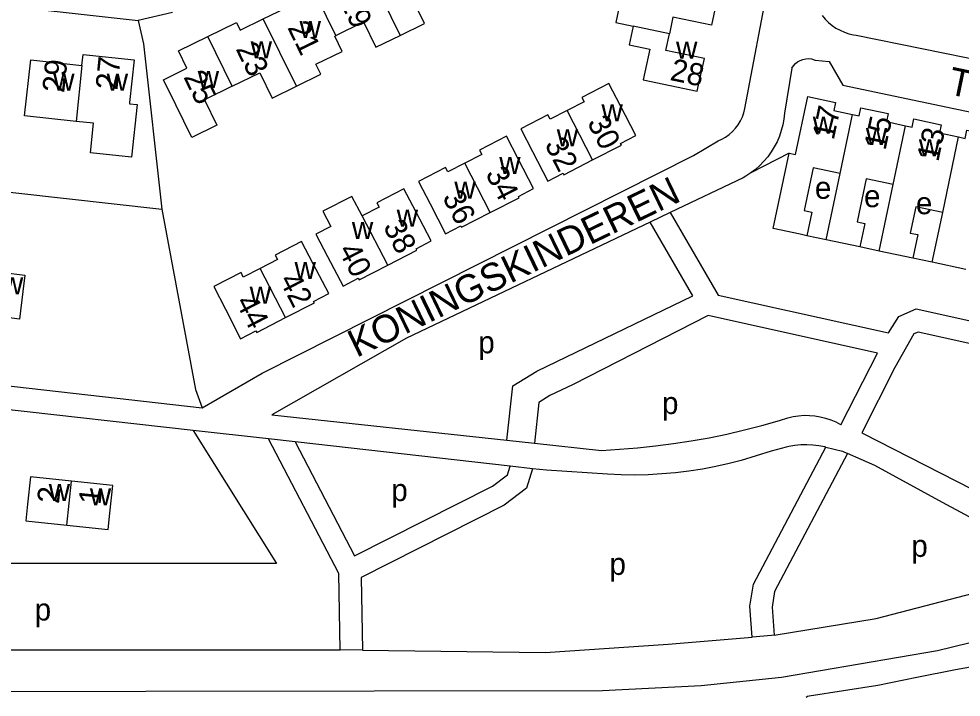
# Model space of a CAD drawing. Extents: x 159441 to 162086, y 388175 to 389787.
# Drawn here: x 161523.9 to 161694.2, y 388347.3 to 388469.9 of the extents above; entities that cross this region are included whole.
import ezdxf

# ---------------------------------------------------------------- set-up
doc = ezdxf.new("R2010")
doc.units = 0
for name, color, linetype in [('BLT_Basislijn', 7, 'Continuous'), ('BLT_Bebouwing', 7, 'Continuous'), ('BLT_Centroide', 7, 'Continuous'), ('BLT_Huisnummer', 7, 'Continuous'), ('BLT_Huisnummer_ tussenligend', 7, 'Continuous'), ('BLT_Onderverdeling_panden', 7, 'Continuous'), ('BLT_Straatnaam', 7, 'Continuous')]:
    doc.layers.add(name, color=color, linetype=linetype)

msp = doc.modelspace()

# ---------------------------------------------------------------- linework, layer by layer
at = {"layer": 'BLT_Basislijn'}
for p, q in [((161663.59, 388460.99), (161662.25, 388452.85)), ((161641.62, 388434.91), (161638, 388433.18)), ((161555.41, 388395.51), (161495.67, 388402.23)), ((161573.83, 388393.44), (161569.03, 388393.98)), ((161612.09, 388393.76), (161617.07, 388393.23)), ((161616.74, 388388.61), (161612.7, 388389.07)), ((161585.99, 388355.8), (161581.99, 388355.85))]:
    msp.add_line(p, q, dxfattribs=at)
for points in [[(161557.01, 388399.62), (161567.87, 388405.86), (161645.85, 388445.21), (161650.29, 388447.83), (161650.94, 388448.13), (161651.64, 388448.53), (161652.29, 388449), (161652.89, 388449.54), (161653.43, 388450.12), (161653.91, 388450.77), (161654.33, 388451.45), (161654.68, 388452.18), (161654.95, 388452.93), (161655.14, 388453.71), (161663.91, 388500)], [(161328.88, 388459.92), (161332.73, 388492.8), (161435.01, 388481.49), (161524.85, 388471.88), (161545.47, 388469.62)], [(161551.69, 388471.03), (161545.47, 388469.62)], [(161545.47, 388469.62), (161546.41, 388465.4), (161549.75, 388435.53)], [(161669.1, 388470.52), (161669.64, 388469.86), (161670.23, 388469.26), (161670.88, 388468.71), (161671.58, 388468.23), (161672.33, 388467.82), (161673.1, 388467.47), (161673.91, 388467.21), (161674.74, 388467.02), (161675.22, 388466.94), (161698.95, 388462.12)], [(161663.59, 388460.99), (161663.89, 388461.43), (161664.24, 388461.81), (161664.65, 388462.13), (161665.11, 388462.38), (161665.6, 388462.56), (161666.11, 388462.67), (161666.63, 388462.7), (161667.15, 388462.64), (161667.65, 388462.51), (161667.8, 388462.45)], [(161667.8, 388462.45), (161670.33, 388462.2), (161672.85, 388457.91), (161744.15, 388442.93)], [(161328.88, 388459.92), (161341.81, 388458.77), (161549.75, 388435.53)], [(161662.25, 388452.85), (161662.14, 388451.79), (161661.95, 388450.74), (161661.69, 388449.7), (161661.35, 388448.69), (161660.93, 388447.7), (161660.44, 388446.75), (161659.88, 388445.84), (161659.26, 388444.97), (161658.57, 388444.15), (161657.82, 388443.39), (161657.02, 388442.68), (161656.17, 388442.04)], [(161663.12, 388445.64), (161656.17, 388442.04)], [(161641.62, 388434.91), (161650.27, 388419.97), (161681.07, 388413.13), (161682.92, 388416.13), (161686.07, 388417.48), (161748.77, 388403.58), (161749.41, 388403.67), (161750.3, 388405.26), (161762.33, 388432.28), (161760.67, 388433.58), (161755.49, 388443.93)], [(161656.17, 388442.04), (161655.27, 388441.46), (161654.78, 388441.18), (161641.62, 388434.91)], [(161549.75, 388435.53), (161555.81, 388402.9), (161557.01, 388399.62)], [(161638, 388433.18), (161593.99, 388412.2), (161569.65, 388398.33), (161612.09, 388393.76)], [(161612.09, 388393.76), (161613.18, 388403.56), (161617.5, 388406.22), (161645.73, 388419.84), (161638, 388433.18)], [(161669.81, 388429.96), (161666.29, 388430.71)], [(161679.39, 388427.93), (161675.87, 388428.68)], [(161688.96, 388425.9), (161685.45, 388426.65)], [(161325.51, 388426.05), (161325.92, 388425.85), (161557.01, 388399.62)], [(161617.07, 388393.23), (161629.18, 388391.92), (161632.45, 388392.11), (161635.71, 388392.37), (161638.96, 388392.71), (161642.2, 388393.13), (161645.43, 388393.63), (161648.65, 388394.21), (161651.86, 388394.87), (161655.05, 388395.61), (161658.21, 388396.42), (161661.36, 388397.31), (161662.9, 388397.78), (161663.86, 388398.01), (161664.83, 388398.17), (161665.81, 388398.25), (161666.79, 388398.24), (161667.77, 388398.16), (161668.74, 388398), (161669.7, 388397.76), (161670.63, 388397.45), (161671.53, 388397.05), (161672.4, 388396.59), (161672.49, 388396.54), (161679.08, 388409.47), (161648.47, 388416.28), (161624.07, 388403.85), (161619.89, 388401.82), (161617.88, 388400.59), (161617.07, 388393.23)], [(161748.62, 388399.51), (161686.46, 388413.3), (161685.66, 388412.95), (161682.25, 388406.88), (161676.24, 388395.08), (161704.72, 388380.56)], [(161825.3, 388398.51), (161820.15, 388396.26), (161815.22, 388394.54), (161712.84, 388361.31), (161689.93, 388355.71), (161661.73, 388350.85), (161647.19, 388349.34), (161629.36, 388348.46), (161381.74, 388348.09), (161372.15, 388347.92), (161363.21, 388348.43), (161354.77, 388349.2), (161344.3, 388349.46), (161332.03, 388349.71), (161319.76, 388350.22), (161309.54, 388350.22), (161304.37, 388350.34)], [(161555.41, 388395.51), (161570.48, 388371.48), (161500.96, 388371.48), (161494.67, 388371.46)], [(161569.03, 388393.98), (161555.41, 388395.51)], [(161581.99, 388355.85), (161581.74, 388369.68), (161569.03, 388393.98)], [(161612.7, 388389.07), (161573.83, 388393.44)], [(161573.83, 388393.44), (161584.59, 388372.86), (161609.5, 388385.45), (161612.23, 388387.5), (161612.7, 388389.07)], [(161669.72, 388392.49), (161669.54, 388392.54), (161668.46, 388392.75), (161667.38, 388392.87), (161666.29, 388392.92), (161665.21, 388392.89), (161664.12, 388392.78), (161663.05, 388392.59), (161662.6, 388392.48), (161659.86, 388391.75), (161657.14, 388390.95), (161654.45, 388390.07), (161652.26, 388389.52), (161649.85, 388388.99), (161647.44, 388388.53), (161645.01, 388388.16), (161642.56, 388387.86), (161640.12, 388387.65), (161637.66, 388387.52), (161635.2, 388387.46), (161632.74, 388387.49), (161630.29, 388387.59), (161619.28, 388388.33), (161616.74, 388388.61)], [(161656.41, 388358.15), (161656.01, 388363.79), (161656.66, 388367.73), (161669.72, 388392.49)], [(161673.65, 388391.36), (161660.5, 388366.43), (161660.03, 388363.6), (161660.39, 388358.51)], [(161660.39, 388358.51), (161678.84, 388361.51), (161702.48, 388367.68), (161705.14, 388368.97), (161705.58, 388369.16), (161705.98, 388369.43), (161706.33, 388369.76), (161706.62, 388370.15), (161706.84, 388370.57), (161706.99, 388371.03), (161707.06, 388371.51), (161707.05, 388371.99), (161706.97, 388372.46), (161706.8, 388372.91), (161706.57, 388373.33), (161706.26, 388373.71), (161705.9, 388374.03), (161705.64, 388374.2), (161700.61, 388377.23), (161690.86, 388382.48), (161678.59, 388389.18), (161673.65, 388391.36)], [(161669.72, 388392.49), (161672.77, 388391.76), (161673.65, 388391.36)], [(161666.18, 388347.32), (161666.21, 388347.35), (161666.45, 388347.5), (161666.73, 388347.57), (161679.17, 388349.49), (161686.18, 388350.96), (161693.19, 388352.32), (161696.56, 388352.91), (161721.71, 388357.07), (161772.64, 388373.89), (161801.25, 388383.37), (161821.16, 388389.95)], [(161616.74, 388388.61), (161615.68, 388385.09), (161611.62, 388382.04), (161585.75, 388368.97), (161585.99, 388355.8)], [(161660.39, 388358.51), (161659.93, 388358.44), (161656.41, 388358.15)], [(161585.99, 388355.8), (161619.04, 388355.37), (161641.27, 388356.9), (161656.41, 388358.15)], [(161364.69, 388356.62), (161369.6, 388356.36), (161383.15, 388356.1), (161390.81, 388356.36), (161502.75, 388355.88), (161579.94, 388355.88), (161581.99, 388355.85)]]:
    msp.add_lwpolyline(points, dxfattribs=at)
at = {"layer": 'BLT_Bebouwing'}
for p, q in [((161526.04, 388462.49), (161535.29, 388461.49)), ((161669.81, 388429.96), (161672.33, 388441.97)), ((161679.39, 388427.93), (161681.92, 388439.95)), ((161688.96, 388425.9), (161690.87, 388434.93))]:
    msp.add_line(p, q, dxfattribs=at)
for points in [[(161592.79, 388466.9), (161597.23, 388469.07), (161594.99, 388473.64), (161599.98, 388476.08)], [(161636.78, 388477.35), (161635.64, 388471.99), (161632.53, 388472.65), (161631.8, 388469.22), (161634.91, 388468.56)], [(161568.05, 388469.87), (161572.19, 388471.9), (161571.52, 388473.28), (161576.81, 388475.88)], [(161650.3, 388474.49), (161649.08, 388468.75), (161642.12, 388470.22), (161641.48, 388467.2)], [(161558.05, 388466.69), (161563.24, 388469.23), (161563.91, 388467.85), (161568.05, 388469.87)], [(161581.21, 388466.9), (161586.2, 388469.34), (161588.44, 388464.76), (161592.79, 388466.9)], [(161634.91, 388468.56), (161634.2, 388465.2), (161637.93, 388464.42), (161636.76, 388458.86), (161641.62, 388457.84), (161646.52, 388456.81), (161647.81, 388462.71), (161640.84, 388464.18), (161641.48, 388467.2)], [(161562.44, 388457.71), (161557.45, 388455.27), (161559.7, 388450.69), (161555.16, 388448.47), (161552.25, 388454.37), (161550.04, 388458.86), (161554.29, 388460.96), (161552.74, 388464.09), (161558.05, 388466.69)], [(161574.07, 388457.73), (161578.47, 388459.88), (161577.58, 388461.7), (161582.36, 388464), (161580.99, 388466.79), (161581.21, 388466.9)], [(161534.27, 388451.37), (161524.94, 388452.38), (161526.04, 388462.49)], [(161535.29, 388461.49), (161535.51, 388463.48), (161544.75, 388462.48), (161543.92, 388454.8), (161543.89, 388454.54), (161545.3, 388454.39), (161544.27, 388444.89), (161536.85, 388445.69), (161537.42, 388451.03), (161534.27, 388451.37)], [(161562.44, 388457.71), (161567.43, 388460.15), (161569.67, 388455.57), (161574.07, 388457.73)], [(161627.6, 388444.39), (161632.81, 388447.07), (161632.65, 388447.39), (161635.4, 388448.8), (161632.64, 388454.17), (161630.55, 388458.22), (161625.66, 388455.71), (161626.07, 388454.91), (161623, 388453.33)], [(161663.12, 388445.64), (161664.29, 388445.38), (161666.52, 388455.87)], [(161666.52, 388455.87), (161671.47, 388454.8), (161671.17, 388453.34), (161674.56, 388452.64)], [(161674.56, 388452.64), (161675.78, 388452.38), (161676.08, 388453.84), (161681.03, 388452.79), (161680.71, 388451.32), (161684.15, 388450.59)], [(161623, 388453.33), (161619.94, 388451.75), (161619.52, 388452.55), (161614.63, 388450.04), (161616.74, 388445.93), (161619.51, 388440.57), (161622.25, 388441.98), (161622.39, 388441.71), (161627.6, 388444.39)], [(161684.15, 388450.59), (161685.36, 388450.33), (161685.67, 388451.8), (161690.61, 388450.75), (161690.3, 388449.29), (161693.72, 388448.56)], [(161693.72, 388448.56), (161694.93, 388448.3), (161695.24, 388449.77), (161700.2, 388448.72), (161699.89, 388447.26), (161703.31, 388446.53)], [(161609.1, 388434.9), (161614.3, 388437.56), (161614.18, 388437.82), (161616.92, 388439.23), (161614.16, 388444.61), (161612.06, 388448.71), (161607.17, 388446.19), (161607.58, 388445.39), (161604.53, 388443.82)], [(161666.29, 388430.71), (161665.12, 388430.96), (161660.22, 388432), (161663.12, 388445.64)], [(161604.53, 388443.82), (161601.44, 388442.24), (161601.03, 388443.04), (161596.14, 388440.52), (161598.24, 388436.44), (161601.02, 388431.07), (161603.76, 388432.49), (161603.9, 388432.24), (161609.1, 388434.9)], [(161672.33, 388441.97), (161667.47, 388442.99), (161665.85, 388435.24), (161667.2, 388434.96), (161666.29, 388430.71)], [(161681.92, 388439.95), (161677.06, 388440.98), (161675.43, 388433.21), (161676.78, 388432.93), (161675.87, 388428.68)], [(161590.6, 388425.41), (161595.8, 388428.07), (161595.68, 388428.32), (161598.43, 388429.76), (161595.62, 388435.11), (161593.5, 388439.16), (161588.61, 388436.65), (161589.02, 388435.85), (161585.95, 388434.27)], [(161585.95, 388434.27), (161584.07, 388437.82), (161578.84, 388435.13), (161580.26, 388432.36), (161577.58, 388430.97), (161579.69, 388426.95), (161582.49, 388421.6), (161585.24, 388423.04), (161585.4, 388422.74), (161590.6, 388425.41)], [(161690.87, 388434.93), (161686.01, 388435.95), (161685, 388431.18), (161686.35, 388430.9), (161685.45, 388426.65)], [(161572.1, 388415.9), (161577.31, 388418.57), (161577.18, 388418.83), (161579.92, 388420.27), (161577.12, 388425.62), (161575, 388429.65), (161570.21, 388427.18), (161570.62, 388426.38), (161567.54, 388424.81)], [(161675.87, 388428.68), (161669.81, 388429.96)], [(161685.45, 388426.65), (161679.39, 388427.93)], [(161695.04, 388424.61), (161688.96, 388425.9)], [(161517.64, 388424.51), (161525.01, 388423.59), (161524.64, 388420.61), (161524.02, 388415.65), (161516.64, 388416.58)], [(161567.54, 388424.81), (161564.47, 388423.24), (161564.06, 388424.04), (161559.16, 388421.54), (161561.24, 388417.46), (161563.99, 388412.08), (161566.72, 388413.54), (161566.89, 388413.24), (161572.1, 388415.9)], [(161533.44, 388386.36), (161526, 388387.15), (161525.47, 388382.18), (161525.15, 388379.2), (161532.59, 388378.4)], [(161532.59, 388378.4), (161540.02, 388377.61), (161540.34, 388380.59), (161540.87, 388385.56), (161533.44, 388386.36)]]:
    msp.add_lwpolyline(points, dxfattribs=at)
at = {"layer": 'BLT_Onderverdeling_panden'}
for p, q in [((161587.69, 388477.31), (161592.79, 388466.9)), ((161581.21, 388466.9), (161576.81, 388475.88)), ((161574.07, 388457.73), (161568.05, 388469.87)), ((161641.48, 388467.2), (161634.91, 388468.56)), ((161562.44, 388457.71), (161558.05, 388466.69)), ((161535.29, 388461.49), (161534.27, 388451.37)), ((161627.6, 388444.39), (161623, 388453.33)), ((161672.33, 388441.97), (161674.56, 388452.64)), ((161681.92, 388439.95), (161684.15, 388450.59)), ((161690.87, 388434.93), (161693.72, 388448.56)), ((161609.1, 388434.9), (161604.53, 388443.82)), ((161590.6, 388425.41), (161585.95, 388434.27)), ((161572.1, 388415.9), (161567.54, 388424.81)), ((161532.59, 388378.4), (161533.44, 388386.36))]:
    msp.add_line(p, q, dxfattribs=at)

# ---------------------------------------------------------------- texts
at = {"layer": 'BLT_Centroide'}
for s, p in [('w', (161574.64, 388466.41)), ('w', (161565.79, 388462.75)), ('w', (161642.68, 388462.69)), ('w', (161530.11, 388456.94)), ('w', (161539.78, 388456.89)), ('w', (161556.23, 388457.41)), ('w', (161629.2, 388451.38)), ('w', (161667.39, 388449.14)), ('w', (161621.12, 388446.88)), ('w', (161676.98, 388447.12)), ('w', (161686.56, 388445.08)), ('w', (161610.72, 388441.88)), ('w', (161602.62, 388437.38)), ('e', (161667.77, 388437.38)), ('e', (161676.65, 388435.86)), ('e', (161686.03, 388434.59)), ('w', (161592.19, 388432.36)), ('w', (161584.09, 388430.11)), ('w', (161573.73, 388422.88)), ('w', (161520.83, 388420.09)), ('w', (161565.62, 388418.41)), ('p', (161606.93, 388409.46)), ('p', (161640.14, 388398.48)), ('w', (161529.3, 388382.78)), ('p', (161591.21, 388382.76)), ('w', (161536.73, 388381.98)), ('p', (161685.2, 388372.67)), ('p', (161630.65, 388369.41)), ('p', (161526.76, 388361.17))]:
    msp.add_text(s, height=4, dxfattribs=at).set_placement(p)
at = {"layer": 'BLT_Huisnummer'}
for s, rotation, p in [('19', 296.0913, (161581.74, 388473.16)), ('29', 84.2159, (161532.09, 388456.43)), ('27', 84.2159, (161541.71, 388456.93)), ('28', 348.031, (161641.43, 388458.87)), ('25', 296.0913, (161553.59, 388459.4)), ('17', 78.0158, (161671.17, 388447.86)), ('30', 297.2354, (161626.54, 388451.19)), ('32', 297.2354, (161618.86, 388447.23)), ('34', 297.2354, (161608.15, 388441.94)), ('36', 297.2354, (161600.37, 388437.68)), ('38', 297.2354, (161589.67, 388432.38)), ('40', 297.2354, (161581.57, 388428.12)), ('42', 297.2354, (161570.88, 388422.71)), ('44', 297.2354, (161562.98, 388418.77)), ('2', 83.913, (161531.14, 388382.17)), ('1', 83.913, (161538.65, 388382))]:
    msp.add_text(s, height=4, rotation=rotation, dxfattribs=at).set_placement(p)
at = {"layer": 'BLT_Huisnummer_ tussenligend'}
for s, rotation, p in [('21', 296.0913, (161572.37, 388468.34)), ('23', 296.0913, (161563.03, 388464.49)), ('15', 78.0158, (161680.52, 388446.01)), ('13', 78.0158, (161690.07, 388443.93))]:
    msp.add_text(s, height=4, rotation=rotation, dxfattribs=at).set_placement(p)
at = {"layer": 'BLT_Straatnaam'}
for s, rotation, p in [('TONDELDOOS', 348.265, (161691.6, 388456.34)), ('KONINGSKINDEREN', 25.7877, (161584.95, 388408.61))]:
    msp.add_text(s, height=5, rotation=rotation, dxfattribs=at).set_placement(p)

doc.saveas('drawing.dxf')
